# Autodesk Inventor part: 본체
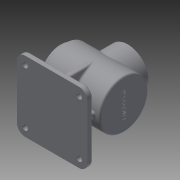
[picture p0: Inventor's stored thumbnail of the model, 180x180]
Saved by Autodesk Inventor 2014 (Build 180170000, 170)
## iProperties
Created: 2015-07
Part Number: 본체
Material: Generic
Document SubType Name: Modeling
Designer: user
Density: 1 g/cm^3
Appearance: Default
Author: user
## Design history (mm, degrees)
node "Sketch1"
sketch "Sketch2"
  geometry: L1 (0, 0)-(110, 0); L2 (0, 0)-(0, 45); L3 (0, 45)-(110, 45); L4 (110, 45)-(110, 0); L5 (7, 0)-(7, 40); L6 (7, 40)-(103, 40); L7 (103, 40)-(103, 0)
  constraints: 14 end point, 4 perpendicular, 2 parallel, 2 point on line, 1 horizontal
  dimensions: "d1" = 110 distance of L1.start L1.end; "d2" = 90 diameter of L3 L1; "d3" = 7 distance between parallel lines of L4 L7; "d4" = 5 distance between parallel lines of L6 L3; "d5" = 96 distance of L5.end L6.end
revolve "Revolution1" sketch "Sketch2" stored, may be unused: angle "d6" = 90 deg
sketch "Sketch3"
  geometry: C1 r 45 at (0, 0) reference; C2 r 38 at (0, 0)
  constraints: 1 centre point, 1 coincident
  dimensions: "d7" = 76 diameter of C2
extrude "Extrusion1" join sketch "Sketch3" distance "d8" = 7; taper "d9" = 0 deg
hole "Hole1" diameter "d12" = 54; stored, may be unused: countersink angle "d16" = 90 deg, drill point angle "d18" = 0 deg; dims "d10" = 10, "d11" = 10, "d13" = 6, "d14" = 4, "d15" = 2, "d17" = 14
workplane "Work Plane1"
sketch "Sketch4"
  geometry: L1 (10, 65)-(-120, 65); L2 (-120, 65)-(-120, -65); L3 (-120, -65)-(10, -65); L4 (10, -65)-(10, 65); L5 (10, 65)-(-120, -65); L6 (-120, 65)-(10, -65); L7 (0, 0)-(-55, 0); 1 further point
  constraints: 14 end point, 2 horizontal, 2 midpoint, 2 parallel, 1 coincident, 1 perpendicular
  dimensions: "d20" = 130 distance of L1.start L1.end; "d21" = 130 distance of L1.end L2.end; "d22" = 55 distance of L7.start L7.end
extrude "Extrusion2" join sketch "Sketch4" distance "d23" = 10; taper "d24" = 0 deg
sketch "Sketch5"
  geometry: L1 (-10, -65)-(120, -65) reference; L2 (120, -65)-(120, 65) reference; L3 (120, 65)-(-10, 65) reference; L4 (-10, 65)-(-10, -65) reference; L5 (-10, -65)-(120, -65) reference; L6 (-10, 65)-(-10, -65) reference; L7 (120, 65)-(-10, 65) reference; L8 (120, -65)-(120, 65) reference; L9 (5, 50)-(105, 50); L10 (105, 50)-(105, -50); L11 (105, -50)-(5, -50); L12 (5, -50)-(5, 50); C1 r 7.5 at (105, 50); C2 r 7.5 at (5, -50); C3 r 7.5 at (105, -50); C4 r 7.5 at (5, 50); 1 further point
  constraints: 8 end point, 4 centre point, 4 coincident, 3 other
  dimensions: "d26" = 5 distance from line of L12 point (0, 0); "d28" = 15 diameter of C1; "d29" = 15 diameter of C2; "d30" = 15 diameter of C3; "d31" = 15 diameter of C4
extrude "Extrusion3" join sketch "Sketch5" distance "d32" = 3; taper "d33" = 0 deg
hole "Hole2" diameter "d36" = 10; stored, may be unused: countersink angle "d40" = 90 deg, drill point angle "d42" = 0 deg; dims "d34" = 10, "d35" = 10, "d37" = 6, "d38" = 4, "d39" = 2, "d41" = 10
hole "Hole3" diameter "d45" = 10; stored, may be unused: countersink angle "d49" = 90 deg, drill point angle "d51" = 0 deg; dims "d43" = 10, "d44" = 10, "d46" = 6, "d47" = 4, "d48" = 2, "d50" = 10
hole "Hole4" diameter "d54" = 10; stored, may be unused: countersink angle "d58" = 90 deg, drill point angle "d60" = 0 deg; dims "d52" = 10, "d53" = 10, "d55" = 6, "d56" = 4, "d57" = 2, "d59" = 10
hole "Hole5" diameter "d63" = 10; stored, may be unused: countersink angle "d67" = 90 deg, drill point angle "d69" = 0 deg; dims "d61" = 10, "d62" = 10, "d64" = 6, "d65" = 4, "d66" = 2, "d68" = 10
sketch "Sketch6"
  geometry: L1 (50, 5)-(60, 5); L2 (60, 5)-(60, -5); L3 (60, -5)-(50, -5); L4 (50, -5)-(50, 5); L5 (50, 5)-(60, -5); L6 (60, 5)-(50, -5); L7 (55, 0)-(0, 0); 1 further point
  constraints: 14 end point, 4 midpoint, 2 horizontal, 2 parallel, 1 perpendicular
  dimensions: "d70" = 10 distance of L2.end L3.end; "d71" = 10 distance of L1.end L2.end; "d72" = 55 distance of L7.start L7.end
extrude "Extrusion4" join sketch "Sketch6" stored distance "d73" = 3; taper "d74" = 0 deg
sketch "Sketch7"
  geometry: L1 (0, -45)-(110, -45) reference; L2 (120, -68)-(-10, -68) reference; L3 (10, -45)-(10, -68); 1 further point
  constraints: 2 end point, 2 point on line, 1 perpendicular
  dimensions: "d75" = 10 distance from line of L3 point (0, 0)
feature "Rib1" sketch "Sketch7" dims "d76" = 1, "d77" = 10, "d78" = 0, "d79" = 0, "d80" = 1, "d81" = 1
workplane "Work Plane2"
mirror "Mirror1"
sketch "Sketch8"
  geometry: L1 (-45, 0)-(-45, -68); L2 (-65, -68)-(65, -68) reference; 1 further point
  constraints: 2 end point, 1 point on line, 1 vertical
  dimensions: "d82" = 68 distance of L1.start L1.end; "d83" = 45 distance from line of point (0, 0) L1
feature "Rib2" sketch "Sketch8" dims "d84" = 1, "d85" = 10, "d86" = 0, "d87" = 0, "d88" = 1, "d89" = 1
mirror "Mirror2"
workplane "Work Plane3"
sketch "Sketch9"
  geometry: L1 (0, 0)-(55, 0); C1 r 38 at (55, 0)
  constraints: 2 end point, 1 centre point, 1 coincident, 1 horizontal
  dimensions: "d91" = 55 distance of L1.start L1.end; "d92" = 76 diameter of C1
extrude "Extrusion5" join sketch "Sketch9" stored distance "d93" = 3; taper "d94" = 0 deg
hole "Hole6" diameter "d97" = 54; stored, may be unused: countersink angle "d101" = 90 deg, drill point angle "d103" = 0 deg; dims "d95" = 10, "d96" = 10, "d98" = 6, "d99" = 4, "d100" = 2, "d102" = 10
sketch "Sketch11"
  geometry: L1 (0, 32)-(0, -32); L2 (-32, 0)-(32, 0); A1 r 32 centre (0, 0) between (0, 32) and (32, 0); 2 further points
  constraints: 6 midpoint, 4 end point, 4 point on circle, 1 centre point, 1 perpendicular, 1 vertical
  dimensions: "d114" = 64 diameter of A1
hole "Hole8" sketch "Sketch11" at (32, 0), (0, 32), (0, -32), (-32, 0) diameter "d115" = 3.242; stored, may be unused: countersink angle "d119" = 90 deg, drill point angle "d121" = 118 deg; dims "d116" = 8, "d117" = 4, "d118" = 2, "d120" = 10
sketch "Sketch12"
  geometry: C1 r 45 at (0, 0) reference; 1 further point
  constraints: 1 coincident, 1 other
emboss "Emboss1" sketch "Sketch12" dims "d122" = 0.5, "d123" = 0
fillet "Fillet1" dims "d124" = 15
fillet "Fillet2" dims "d125" = 3
fillet "Fillet3" dims "d126" = 3
fillet "Fillet4" dims "d127" = 3
fillet "Fillet5" dims "d128" = 3
chamfer "Chamfer1" distance "d129" = 1; stored, may be unused: second distance "d130" = 2, angle "d131" = 45 deg
fillet "Fillet6" dims "d132" = 3
fillet "Fillet7" dims "d133" = 3
chamfer "Chamfer2" distance "d134" = 1; stored, may be unused: second distance "d135" = 2, angle "d136" = 45 deg
sketch "Sketch13"
  geometry: L1 (0, 32)-(0, -32); C1 r 38 at (0, 0) reference; A1 r 32 centre (0, 0) between (0, 32) and (0, -32); 1 further point
  constraints: 2 end point, 2 point on circle, 1 centre point, 1 coincident, 1 midpoint, 1 vertical
  dimensions: "d137" = 64 diameter of A1
hole "Hole9" sketch "Sketch13" at (0, 32) diameter "d138" = 3.242; stored, may be unused: countersink angle "d142" = 90 deg, drill point angle "d144" = 118 deg; dims "d139" = 8, "d140" = 4, "d141" = 2, "d143" = 10
pattern_circular "Circular Pattern1" dims angle "d146" = 360 deg
body "Solid1"
node "Projected Loop1"
other parameters: "d19" = -78
